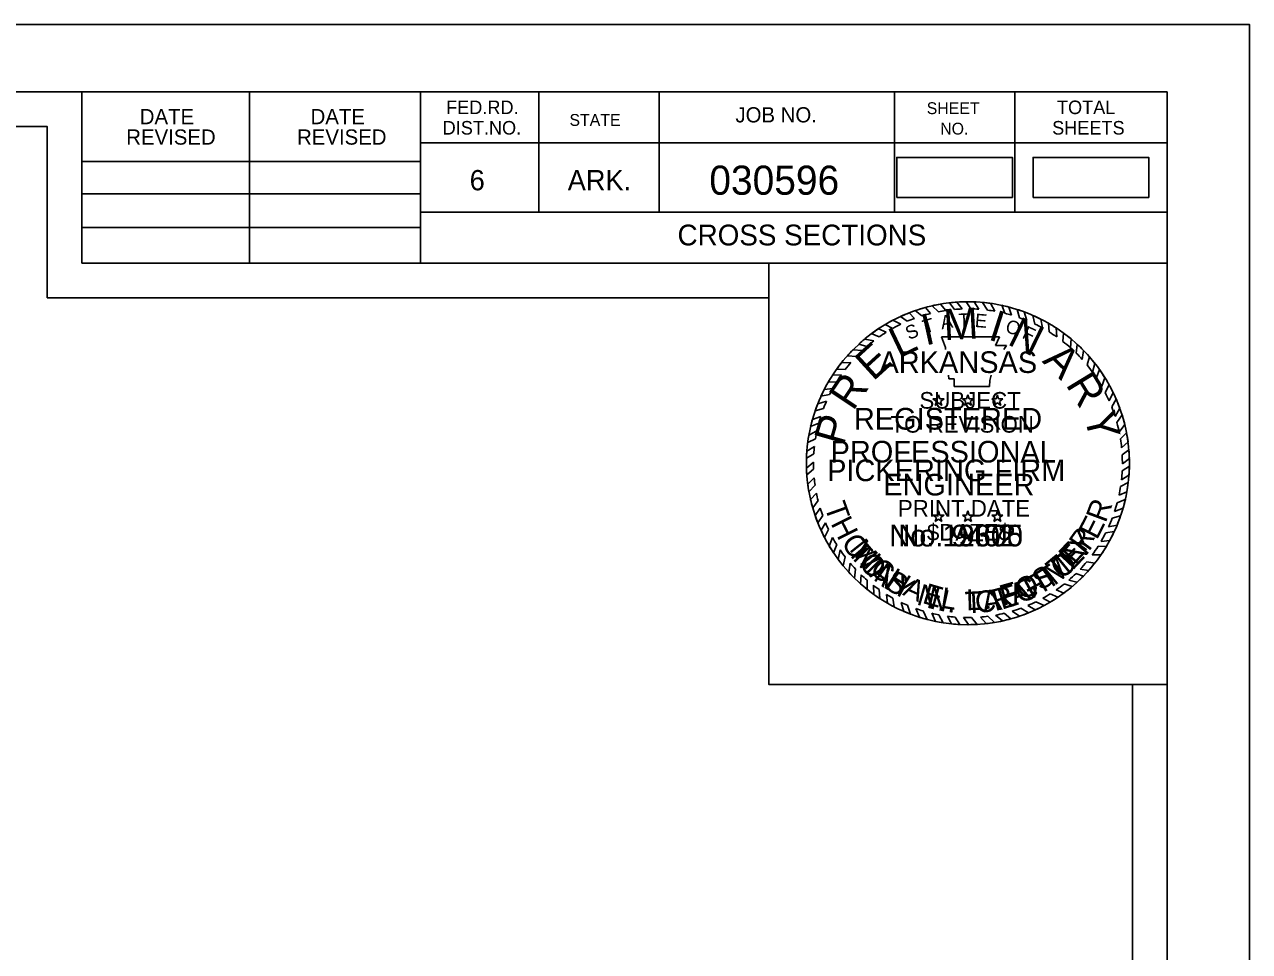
# Model space of a CAD drawing. Extents: x 1368910 to 1369601, y 380116 to 380950.
# Drawn here: x 1369172.5 to 1369243.2, y 380470.2 to 380523.8 of the extents above; entities that cross this region are included whole.
import ezdxf

# ---------------------------------------------------------------- set-up
doc = ezdxf.new("R2010")
doc.units = 0
for name, color, linetype in [('Notes', 7, 'Continuous'), ('R_Border', 7, 'Continuous'), ('R_Border Notes', 7, 'Continuous'), ('R_No Plot', 7, 'Continuous'), ('STAMP_PE_CRAFTON', 7, 'Continuous'), ('STAMP_PE_FOSTER', 7, 'Continuous'), ('STAMP_PE_SEAL-INFO', 7, 'Continuous'), ('STAMP_PE_TAEGTMEYER', 7, 'Continuous'), ('STAMP_PE_TXT', 7, 'Continuous'), ('STAMP_PRELIMINARY', 7, 'Continuous')]:
    doc.layers.add(name, color=color, linetype=linetype)

msp = doc.modelspace()

# ---------------------------------------------------------------- linework, layer by layer
at = {"layer": 'Notes'}
for points in [[(1369222.812, 380513.786), (1369229.495, 380513.786), (1369229.495, 380516.096), (1369222.812, 380516.096)], [(1369230.682, 380513.786), (1369237.365, 380513.786), (1369237.365, 380516.096), (1369230.682, 380516.096)]]:
    msp.add_lwpolyline(points, close=True, dxfattribs=at)
at = {"layer": 'R_Border'}
for p, q in [((1368922.244, 380519.881), (1369238.424, 380519.881)), ((1369175.784, 380510.001), (1369175.784, 380519.881)), ((1369185.464, 380510.001), (1369185.464, 380519.881)), ((1369195.324, 380519.881), (1369195.324, 380510.001)), ((1369202.164, 380519.881), (1369202.164, 380512.941)), ((1369209.104, 380519.881), (1369209.104, 380512.941)), ((1369222.684, 380519.881), (1369222.684, 380512.941)), ((1369229.624, 380519.881), (1369229.624, 380512.941)), ((1369238.424, 380314.421), (1369238.424, 380519.881)), ((1369238.424, 380516.941), (1369195.324, 380516.941)), ((1369238.424, 380516.961), (1369238.424, 380516.961)), ((1369175.784, 380515.861), (1369195.324, 380515.861)), ((1369175.784, 380514.001), (1369195.324, 380514.001)), ((1369238.424, 380512.941), (1369195.324, 380512.941)), ((1369198.284, 380512.941), (1369238.424, 380512.941)), ((1369175.784, 380512.061), (1369195.324, 380512.061)), ((1369238.424, 380510.001), (1369175.784, 380510.001))]:
    msp.add_line(p, q, dxfattribs=at)
at = {"layer": 'R_No Plot'}
for points in [[(1368909.836, 380523.775), (1369243.176, 380523.775), (1369243.176, 380310.438), (1368909.836, 380310.438)], [(1369236.424, 380419.151), (1368924.244, 380419.151), (1368924.244, 380517.881), (1369173.784, 380517.881), (1369173.784, 380508.001), (1369191.324, 380508.001), (1369215.424, 380508.001), (1369215.424, 380485.668), (1369236.424, 380485.668)], [(1368924.244, 380517.881), (1369173.784, 380517.881), (1369173.784, 380508.001), (1369191.324, 380508.001), (1369215.424, 380508.001), (1369215.424, 380485.668), (1369236.424, 380485.668), (1369236.424, 380316.421), (1368924.244, 380316.421)], [(1369215.424, 380510.001), (1369238.424, 380510.001), (1369238.424, 380485.668), (1369215.424, 380485.668)]]:
    msp.add_lwpolyline(points, close=True, dxfattribs=at)
at = {"layer": 'STAMP_PE_SEAL-INFO'}
for p, q in [((1369225.86, 380507.705), (1369226.141, 380507.322)), ((1369226.595, 380507.351), (1369226.283, 380507.744)), ((1369227.093, 380507.355), (1369226.815, 380507.765)), ((1369227.551, 380507.335), (1369227.293, 380507.759)), ((1369228.057, 380507.284), (1369227.765, 380507.728)), ((1369228.483, 380507.219), (1369228.225, 380507.675)), ((1369223.535, 380507.128), (1369223.83, 380506.803)), ((1369223.883, 380507.256), (1369224.264, 380506.951)), ((1369224.474, 380507.438), (1369224.762, 380507.091)), ((1369224.862, 380507.535), (1369225.218, 380507.192)), ((1369225.344, 380507.631), (1369225.643, 380507.264)), ((1369229.045, 380507.101), (1369228.871, 380507.56)), ((1369229.447, 380506.992), (1369229.287, 380507.461)), ((1369229.898, 380506.846), (1369229.757, 380507.325)), ((1369230.317, 380506.686), (1369230.172, 380507.182)), ((1369230.778, 380506.48), (1369230.675, 380506.978)), ((1369222.149, 380506.45), (1369222.581, 380506.227)), ((1369222.597, 380506.701), (1369223.06, 380506.476)), ((1369223.028, 380506.913), (1369223.417, 380506.638)), ((1369231.224, 380506.251), (1369231.137, 380506.76)), ((1369231.611, 380506.025), (1369231.572, 380506.525)), ((1369232.046, 380505.738), (1369232.015, 380506.253)), ((1369220.965, 380505.613), (1369221.494, 380505.512)), ((1369221.341, 380505.94), (1369221.797, 380505.735)), ((1369221.762, 380506.207), (1369222.204, 380506.004)), ((1369225.397, 380505.735), (1369228.741, 380505.735)), ((1369225.518, 380505.427), (1369225.397, 380505.735)), ((1369228.741, 380505.735), (1369228.516, 380505.243)), ((1369232.406, 380505.471), (1369232.441, 380505.958)), ((1369232.853, 380505.099), (1369232.873, 380505.621)), ((1369220.285, 380504.989), (1369220.83, 380504.948)), ((1369220.621, 380505.313), (1369221.08, 380505.174)), ((1369225.622, 380505.13), (1369225.518, 380505.427)), ((1369225.629, 380505.015), (1369225.622, 380505.13)), ((1369228.516, 380505.243), (1369229.148, 380505.243)), ((1369229.148, 380505.243), (1369229.003, 380505.015)), ((1369233.166, 380504.806), (1369233.235, 380505.305)), ((1369233.525, 380504.433), (1369233.591, 380504.959)), ((1369219.617, 380504.233), (1369220.166, 380504.256)), ((1369219.963, 380504.645), (1369220.484, 380504.606)), ((1369233.798, 380504.117), (1369233.935, 380504.588)), ((1369234.122, 380503.7), (1369234.258, 380504.199)), ((1369219.104, 380503.52), (1369219.62, 380503.553)), ((1369219.339, 380503.864), (1369219.844, 380503.859)), ((1369225.82, 380503.306), (1369225.794, 380503.524)), ((1369228.258, 380503.524), (1369228.18, 380503.214)), ((1369234.342, 380503.384), (1369234.52, 380503.848)), ((1369218.627, 380502.695), (1369219.125, 380502.76)), ((1369218.858, 380503.119), (1369219.347, 380503.139)), ((1369226.135, 380503.306), (1369225.82, 380503.306)), ((1369226.135, 380502.876), (1369226.135, 380503.306)), ((1369228.164, 380502.876), (1369226.135, 380502.876)), ((1369228.18, 380503.214), (1369228.164, 380502.876)), ((1369234.65, 380502.887), (1369234.833, 380503.378)), ((1369234.85, 380502.521), (1369235.076, 380502.965)), ((1369218.255, 380501.874), (1369218.759, 380502.02)), ((1369218.439, 380502.307), (1369218.942, 380502.41)), ((1369235.081, 380502.037), (1369235.307, 380502.521)), ((1369235.221, 380501.699), (1369235.485, 380502.133)), ((1369218.105, 380501.468), (1369218.589, 380501.604)), ((1369235.416, 380501.15), (1369235.687, 380501.625)), ((1369217.844, 380500.557), (1369218.314, 380500.75)), ((1369217.948, 380500.965), (1369218.426, 380501.134)), ((1369235.524, 380500.786), (1369235.818, 380501.238)), ((1369235.657, 380500.227), (1369235.976, 380500.674)), ((1369218.208, 380500.311), (1369217.743, 380500.062)), ((1369235.726, 380499.847), (1369236.079, 380500.2)), ((1369218.063, 380499.417), (1369217.627, 380499.136)), ((1369218.122, 380499.852), (1369217.677, 380499.63)), ((1369235.792, 380499.338), (1369236.165, 380499.674)), ((1369235.824, 380498.92), (1369236.215, 380499.212)), ((1369218.01, 380498.498), (1369217.605, 380498.163)), ((1369218.027, 380498.992), (1369217.606, 380498.735)), ((1369235.837, 380498.402), (1369236.242, 380498.723)), ((1369218.017, 380498.091), (1369217.626, 380497.767)), ((1369235.826, 380497.997), (1369236.245, 380498.274)), ((1369218.05, 380497.596), (1369217.679, 380497.239)), ((1369218.102, 380497.167), (1369217.748, 380496.794)), ((1369235.736, 380497.102), (1369236.179, 380497.321)), ((1369235.786, 380497.49), (1369236.22, 380497.747)), ((1369218.181, 380496.708), (1369217.841, 380496.34)), ((1369235.537, 380496.15), (1369236.009, 380496.352)), ((1369235.645, 380496.602), (1369236.1, 380496.797)), ((1369218.274, 380496.289), (1369217.962, 380495.874)), ((1369218.398, 380495.842), (1369218.103, 380495.424)), ((1369235.39, 380495.656), (1369235.88, 380495.857)), ((1369218.539, 380495.419), (1369218.257, 380495.007)), ((1369218.705, 380494.993), (1369218.444, 380494.57)), ((1369235.255, 380495.276), (1369235.738, 380495.407)), ((1369218.877, 380494.609), (1369218.649, 380494.148)), ((1369234.88, 380494.425), (1369235.368, 380494.494)), ((1369235.041, 380494.762), (1369235.529, 380494.858)), ((1369219.112, 380494.151), (1369218.921, 380493.661)), ((1369219.348, 380493.747), (1369219.164, 380493.276)), ((1369234.436, 380493.646), (1369234.914, 380493.64)), ((1369234.608, 380493.927), (1369235.109, 380493.981)), ((1369219.55, 380493.435), (1369219.44, 380492.883)), ((1369219.831, 380493.045), (1369219.729, 380492.514)), ((1369234.097, 380493.152), (1369234.601, 380493.155)), ((1369220.135, 380492.667), (1369220.048, 380492.147)), ((1369220.437, 380492.33), (1369220.375, 380491.808)), ((1369233.406, 380492.325), (1369233.883, 380492.24)), ((1369233.789, 380492.758), (1369234.25, 380492.679)), ((1369220.76, 380492.005), (1369220.73, 380491.475)), ((1369221.104, 380491.692), (1369221.101, 380491.163)), ((1369221.464, 380491.397), (1369221.483, 380490.873)), ((1369232.474, 380491.469), (1369232.942, 380491.324)), ((1369232.745, 380491.693), (1369233.216, 380491.565)), ((1369233.151, 380492.066), (1369233.592, 380491.928)), ((1369221.803, 380491.148), (1369221.839, 380490.63)), ((1369222.23, 380490.866), (1369222.29, 380490.354)), ((1369231.67, 380490.898), (1369232.119, 380490.703)), ((1369232.014, 380491.126), (1369232.452, 380490.937)), ((1369222.58, 380490.66), (1369222.671, 380490.147)), ((1369223.061, 380490.41), (1369223.218, 380489.889)), ((1369223.433, 380490.242), (1369223.606, 380489.731)), ((1369223.926, 380490.049), (1369224.135, 380489.547)), ((1369229.969, 380490.066), (1369230.412, 380489.798)), ((1369230.388, 380490.231), (1369230.812, 380489.97)), ((1369230.848, 380490.44), (1369231.331, 380490.228)), ((1369231.255, 380490.653), (1369231.672, 380490.421)), ((1369224.336, 380489.914), (1369224.562, 380489.425)), ((1369224.844, 380489.776), (1369225.056, 380489.31)), ((1369225.241, 380489.69), (1369225.488, 380489.232)), ((1369225.741, 380489.609), (1369225.981, 380489.168)), ((1369226.178, 380489.561), (1369226.452, 380489.133)), ((1369226.663, 380489.534), (1369226.965, 380489.121)), ((1369227.122, 380489.532), (1369227.466, 380489.136)), ((1369227.641, 380489.559), (1369227.967, 380489.179)), ((1369228.079, 380489.605), (1369228.452, 380489.247)), ((1369228.524, 380489.675), (1369228.913, 380489.335)), ((1369229.017, 380489.779), (1369229.395, 380489.454)), ((1369229.476, 380489.903), (1369229.893, 380489.606))]:
    msp.add_line(p, q, dxfattribs=at)
for radius, start, end in [(9.323, 93.93815, 96.55172), (9.323, 87.72979, 90.67067), (9.323, 81.97315, 84.82355), (9.323, 111.31242, 114.70259), (9.323, 105.23389, 109.03519), (8.914, 104.03521, 107.36155), (9.323, 99.75254, 102.77648), (8.914, 98.25799, 101.03289), (8.914, 92.11016, 95.03666), (8.914, 85.96279, 88.9097), (8.914, 79.92642, 82.69597), (9.323, 75.31251, 77.94263), (8.914, 73.55748, 76.23144), (9.323, 69.60611, 72.30577), (9.323, 63.13288, 66.2704), (9.323, 117.65441, 120.80988), (8.914, 115.68692, 119.15827), (8.914, 110.30864, 113.16588), (8.914, 67.62483, 70.50398), (8.914, 61.15575, 64.37837), (9.323, 56.90029, 60.09423), (9.323, 129.73259, 132.53764), (9.323, 123.61993, 126.59063), (8.914, 121.97456, 125.11001), (8.914, 54.92383, 58.27016), (9.323, 50.3492, 53.71593), (9.323, 135.40208, 138.30314), (8.914, 133.13306, 136.25623), (8.914, 127.52969, 130.96829), (8.914, 48.30163, 52.03953), (9.323, 44.3405, 47.39292), (9.323, 141.60556, 144.44865), (8.914, 139.30101, 142.58729), (8.914, 42.22116, 45.55119), (9.323, 38.12472, 41.23157), (9.323, 147.00719, 149.89904), (8.914, 145.01972, 148.21036), (8.914, 36.13503, 39.53106), (9.323, 31.96138, 35.42937), (8.914, 151.03153, 153.57304), (8.914, 29.90321, 33.66454), (9.323, 25.93909, 29.01247), (9.323, 152.86398, 155.51889), (8.914, 156.34018, 159.23194), (8.914, 23.77322, 27.22114), (9.323, 19.95381, 23.31409), (9.323, 158.40766, 161.07015), (8.914, 17.68022, 21.42509), (9.323, 164.3068, 166.89395), (8.914, 162.43309, 165.00133), (8.914, 11.54445, 15.23639), (9.323, 13.84205, 17.44468), (9.323, 170.0003, 172.68778), (8.914, 167.90481, 170.90393), (9.323, 7.58519, 10.86211), (8.914, 173.73, 176.47337), (8.914, 5.7599, 9.06056), (9.323, 1.72155, 4.72681), (9.323, 175.74093, 178.2066), (8.914, 179.64537, 182.26333), (8.914, 359.73289, 3.06392), (9.323, 181.72508, 184.16255), (8.914, 353.86319, 357.12742), (9.323, 355.71562, 358.95694), (9.323, 187.42037, 190.19271), (8.914, 185.45389, 188.23401), (8.914, 348.07782, 351.34355), (9.323, 349.83047, 353.08845), (9.323, 193.03695, 195.99732), (8.914, 191.22736, 193.98583), (9.323, 343.89247, 347.03502), (8.914, 196.96751, 199.83526), (8.914, 341.77699, 345.09248), (9.323, 198.89671, 201.62812), (8.914, 202.77613, 205.47915), (8.914, 335.6038, 339.18578), (9.323, 337.38367, 340.99332), (9.323, 204.54793, 207.43282), (8.914, 329.55488, 333.20757), (9.323, 331.40371, 334.93315), (9.323, 210.86355, 213.65709), (8.914, 208.78826, 211.79343), (8.914, 323.58513, 327.44069), (9.323, 325.44052, 328.98725), (9.323, 216.61154, 219.49098), (8.914, 214.18375, 217.27474), (9.323, 222.47995, 225.38008), (8.914, 220.39088, 223.30564), (8.914, 316.65308, 320.37109), (9.323, 318.28455, 321.80429), (9.323, 228.36648, 231.34802), (8.914, 226.24938, 229.24068), (8.914, 232.22904, 234.93361), (8.914, 304.82299, 308.51428), (8.914, 310.77436, 314.31605), (9.323, 312.45177, 315.66328), (9.323, 234.29502, 236.94517), (8.914, 238.22227, 240.83529), (8.914, 299.07679, 302.17235), (9.323, 300.62101, 303.87026), (9.323, 306.37206, 310.20799), (9.323, 240.1977, 242.86128), (8.914, 244.32043, 246.94859), (8.914, 250.34912, 253.12157), (8.914, 286.64233, 289.97826), (8.914, 292.87452, 296.11851), (9.323, 294.64808, 298.21662), (9.323, 246.57598, 249.15579), (9.323, 252.59667, 255.32518), (8.914, 256.50505, 259.11916), (9.323, 258.44328, 261.13983), (8.914, 262.37828, 265.20115), (8.914, 268.3215, 271.27698), (8.914, 274.61565, 277.44863), (8.914, 280.34588, 283.58137), (9.323, 282.31994, 285.37019), (9.323, 288.57086, 291.97334), (9.323, 264.19784, 267.10092), (9.323, 270.25484, 273.33609), (9.323, 276.42389, 279.43574)]:
    msp.add_arc((1369226.924, 380498.443), radius, start, end, dxfattribs=at)
at = {"layer": 'STAMP_PE_TXT'}
for p, q in [((1369225.103, 380502.015), (1369224.905, 380502.159)), ((1369224.905, 380502.159), (1369225.15, 380502.159)), ((1369225.027, 380501.782), (1369225.103, 380502.015)), ((1369225.15, 380502.159), (1369225.226, 380502.392)), ((1369225.226, 380502.392), (1369225.301, 380502.159)), ((1369225.301, 380502.159), (1369225.547, 380502.159)), ((1369225.547, 380502.159), (1369225.348, 380502.015)), ((1369225.348, 380502.015), (1369225.424, 380501.782)), ((1369226.801, 380502.015), (1369226.603, 380502.159)), ((1369226.603, 380502.159), (1369226.848, 380502.159)), ((1369226.725, 380501.782), (1369226.801, 380502.015)), ((1369226.848, 380502.159), (1369226.924, 380502.392)), ((1369226.924, 380502.392), (1369226.999, 380502.159)), ((1369226.999, 380502.159), (1369227.245, 380502.159)), ((1369227.245, 380502.159), (1369227.046, 380502.015)), ((1369227.046, 380502.015), (1369227.122, 380501.782)), ((1369228.499, 380502.015), (1369228.301, 380502.159)), ((1369228.301, 380502.159), (1369228.546, 380502.159)), ((1369228.423, 380501.782), (1369228.499, 380502.015)), ((1369228.546, 380502.159), (1369228.622, 380502.392)), ((1369228.622, 380502.392), (1369228.697, 380502.159)), ((1369228.697, 380502.159), (1369228.943, 380502.159)), ((1369228.943, 380502.159), (1369228.744, 380502.015)), ((1369228.744, 380502.015), (1369228.82, 380501.782)), ((1369225.226, 380501.926), (1369225.027, 380501.782)), ((1369225.424, 380501.782), (1369225.226, 380501.926)), ((1369226.924, 380501.926), (1369226.725, 380501.782)), ((1369227.122, 380501.782), (1369226.924, 380501.926)), ((1369228.622, 380501.926), (1369228.423, 380501.782)), ((1369228.82, 380501.782), (1369228.622, 380501.926)), ((1369225.15, 380495.452), (1369225.226, 380495.685)), ((1369225.226, 380495.685), (1369225.301, 380495.452)), ((1369226.848, 380495.452), (1369226.924, 380495.685)), ((1369226.924, 380495.685), (1369226.999, 380495.452)), ((1369228.546, 380495.452), (1369228.622, 380495.685)), ((1369228.622, 380495.685), (1369228.697, 380495.452)), ((1369225.103, 380495.308), (1369224.905, 380495.452)), ((1369224.905, 380495.452), (1369225.15, 380495.452)), ((1369225.027, 380495.075), (1369225.103, 380495.308)), ((1369225.226, 380495.219), (1369225.027, 380495.075)), ((1369225.424, 380495.075), (1369225.226, 380495.219)), ((1369225.301, 380495.452), (1369225.547, 380495.452)), ((1369225.547, 380495.452), (1369225.348, 380495.308)), ((1369225.348, 380495.308), (1369225.424, 380495.075)), ((1369226.801, 380495.308), (1369226.603, 380495.452)), ((1369226.603, 380495.452), (1369226.848, 380495.452)), ((1369226.725, 380495.075), (1369226.801, 380495.308)), ((1369226.924, 380495.219), (1369226.725, 380495.075)), ((1369227.122, 380495.075), (1369226.924, 380495.219)), ((1369226.999, 380495.452), (1369227.245, 380495.452)), ((1369227.245, 380495.452), (1369227.046, 380495.308)), ((1369227.046, 380495.308), (1369227.122, 380495.075)), ((1369228.499, 380495.308), (1369228.301, 380495.452)), ((1369228.301, 380495.452), (1369228.546, 380495.452)), ((1369228.423, 380495.075), (1369228.499, 380495.308)), ((1369228.622, 380495.219), (1369228.423, 380495.075)), ((1369228.82, 380495.075), (1369228.622, 380495.219)), ((1369228.697, 380495.452), (1369228.943, 380495.452)), ((1369228.943, 380495.452), (1369228.744, 380495.308)), ((1369228.744, 380495.308), (1369228.82, 380495.075))]:
    msp.add_line(p, q, dxfattribs=at)
at = {"layer": 'STAMP_PRELIMINARY'}
msp.add_circle((1369226.924, 380498.443), 9.323, dxfattribs=at)

# ---------------------------------------------------------------- texts
at = {"layer": 'R_Border'}
for s, height, p in [('FED.RD.', 0.7819, (1369196.804, 380518.601)), ('JOB NO.', 0.8792, (1369213.504, 380518.121)), ('SHEET', 0.684, (1369224.544, 380518.601)), ('TOTAL', 0.7819, (1369232.064, 380518.601)), ('DATE', 0.8792, (1369179.121, 380518.017)), ('DATE', 0.8792, (1369188.981, 380518.017)), ('STATE', 0.684, (1369203.924, 380517.921)), ('REVISED', 0.8792, (1369178.341, 380516.837)), ('REVISED', 0.8792, (1369188.201, 380516.837)), ('DIST.NO.', 0.7819, (1369196.604, 380517.421)), ('NO.', 0.684, (1369225.324, 380517.421)), ('SHEETS', 0.7819, (1369231.784, 380517.421)), ('6', 1.172, (1369198.164, 380514.201)), ('ARK.', 1.1723, (1369203.824, 380514.201))]:
    msp.add_text(s, height=height, dxfattribs=at).set_placement(p)
at = {"layer": 'R_Border Notes'}
for s, height, p in [('030596', 1.68, (1369211.996, 380513.946)), ('CROSS SECTIONS', 1.2, (1369210.162, 380511.019))]:
    msp.add_text(s, height=height, dxfattribs=at).set_placement(p)
at = {"layer": 'STAMP_PE_CRAFTON'}
msp.add_text('No. 12370', height=1.25, dxfattribs=at).set_placement((1369222.386, 380493.64))
for s, rotation, p in [('T', 310.74416, (1369219.89, 380493.341)), ('N', 49.24107, (1369233.206, 380492.465)), ('O', 317.64216, (1369220.557, 380492.53)), ('O', 41.83906, (1369232.359, 380491.684)), ('N', 324.45371, (1369221.403, 380491.745)), ('Y', 331.16864, (1369222.436, 380491.029)), ('F', 28.78207, (1369230.585, 380490.573)), ('T', 34.11362, (1369231.5, 380491.082)), ('A', 20.51248, (1369229.604, 380490.199)), ('N', 347.47515, (1369224.49, 380490.113)), ('C', 6.01169, (1369227.395, 380489.785)), ('R', 14.81888, (1369228.491, 380489.899)), ('.', 356.89262, (1369225.72, 380489.836))]:
    msp.add_text(s, height=1.25, rotation=rotation, dxfattribs=at).set_placement(p)
at = {"layer": 'STAMP_PE_FOSTER'}
msp.add_text('No. 9402', height=1.25, dxfattribs=at).set_placement((1369222.909, 380493.64))
for s, rotation, p in [('R', 54.5031, (1369233.648, 380493.254)), ('M', 308.33902, (1369220.04, 380493.465)), ('E', 46.96131, (1369232.924, 380492.433)), ('I', 314.18423, (1369220.837, 380492.528)), ('C', 319.87327, (1369221.191, 380492.175)), ('T', 39.41938, (1369232.066, 380491.683)), ('H', 327.72349, (1369222.121, 380491.438)), ('S', 31.72336, (1369231.114, 380491.056)), ('A', 335.72761, (1369223.101, 380490.856)), ('E', 343.5779, (1369224.239, 380490.386)), ('F', 15.86908, (1369228.959, 380490.198)), ('O', 23.71897, (1369230.003, 380490.526)), ('L', 350.81148, (1369225.298, 380490.109)), ('L', 1.26658, (1369226.837, 380489.952)), ('.', 6.80354, (1369227.884, 380490.01))]:
    msp.add_text(s, height=1.2, rotation=rotation, dxfattribs=at).set_placement(p)
at = {"layer": 'STAMP_PE_TAEGTMEYER'}
for s, rotation, p in [('R', 69.57001, (1369234.869, 380494.958)), ('T', 289.64597, (1369218.618, 380495.954)), ('H', 296.73386, (1369218.978, 380494.969)), ('E', 63.0984, (1369234.37, 380493.976)), ('O', 303.77078, (1369219.571, 380493.861)), ('Y', 53.99864, (1369233.701, 380493.036)), ('M', 314.20329, (1369220.226, 380492.91)), ('E', 46.80938, (1369232.962, 380492.221)), ('M', 39.30005, (1369231.922, 380491.342)), ('A', 321.0594, (1369221.187, 380491.945)), ('S', 327.82385, (1369222.014, 380491.301)), ('T', 31.46601, (1369231.024, 380490.798)), ('N', 344.27273, (1369223.91, 380490.295)), ('E', 17.68363, (1369228.874, 380489.975)), ('G', 23.30524, (1369229.923, 380490.305)), ('T', 3.00609, (1369226.788, 380489.764)), ('A', 8.98261, (1369227.835, 380489.819)), ('.', 350.64643, (1369225.123, 380489.963))]:
    msp.add_text(s, height=1.25, rotation=rotation, dxfattribs=at).set_placement(p)
msp.add_text('No. 19605', height=1.25, dxfattribs=at).set_placement((1369222.386, 380493.64))
at = {"layer": 'STAMP_PE_TXT'}
for s, rotation, p in [('A', 9.0679, (1369225.408, 380506.172)), ('T', 1.82479, (1369226.394, 380506.302)), ('E', 355.20019, (1369227.304, 380506.31)), ('S', 23.5541, (1369223.522, 380505.547)), ('T', 16.311, (1369224.445, 380505.919)), ('O', 342.25065, (1369229.031, 380506.033)), ('F', 335.00755, (1369229.996, 380505.695))]:
    msp.add_text(s, height=0.781, rotation=rotation, dxfattribs=at).set_placement(p)
for s, p in [('ARKANSAS', (1369221.816, 380503.654)), ('REGISTERED', (1369220.34, 380500.384)), ('PROFESSIONAL', (1369218.992, 380498.483)), ('ENGINEER', (1369222.033, 380496.581))]:
    msp.add_text(s, height=1.25, dxfattribs=at).set_placement(p)
at = {"layer": 'STAMP_PRELIMINARY'}
for s, rotation, p in [('I', 12.52485, (1369224.461, 380505.23)), ('M', 3.10738, (1369225.559, 380505.539)), ('I', 342.31637, (1369228.027, 380505.606)), ('L', 25.51305, (1369222.932, 380504.471)), ('N', 333.9382, (1369229.135, 380505.332)), ('E', 42.35784, (1369221.45, 380503.14)), ('A', 315.65789, (1369231.168, 380504.307)), ('R', 56.22922, (1369220.294, 380501.407)), ('R', 301.38306, (1369232.536, 380502.993)), ('Y', 283.25926, (1369233.626, 380501.206)), ('P', 73.91301, (1369219.745, 380499.384))]:
    msp.add_text(s, height=1.8, rotation=rotation, dxfattribs=at).set_placement(p)
for s, height, p in [('SUBJECT', 0.96, (1369224.124, 380501.593)), ('TO REVISION', 0.96, (1369222.459, 380500.208)), ('PICKERING FIRM', 1.25, (1369218.797, 380497.407)), ('PRINT DATE', 0.96, (1369222.881, 380495.359)), ('$DATE$', 0.96, (1369224.558, 380493.974))]:
    msp.add_text(s, height=height, dxfattribs=at).set_placement(p)

doc.saveas('drawing.dxf')
